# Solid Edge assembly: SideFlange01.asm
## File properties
Author: ptcarter
Template: Normal.asm
Last saved by: ptcarter
Revision: 17
Application: Solid Edge
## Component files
SideFlange.par
ScrewM8.par
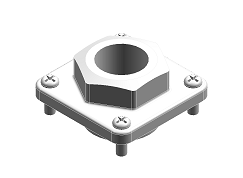
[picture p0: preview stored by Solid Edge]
